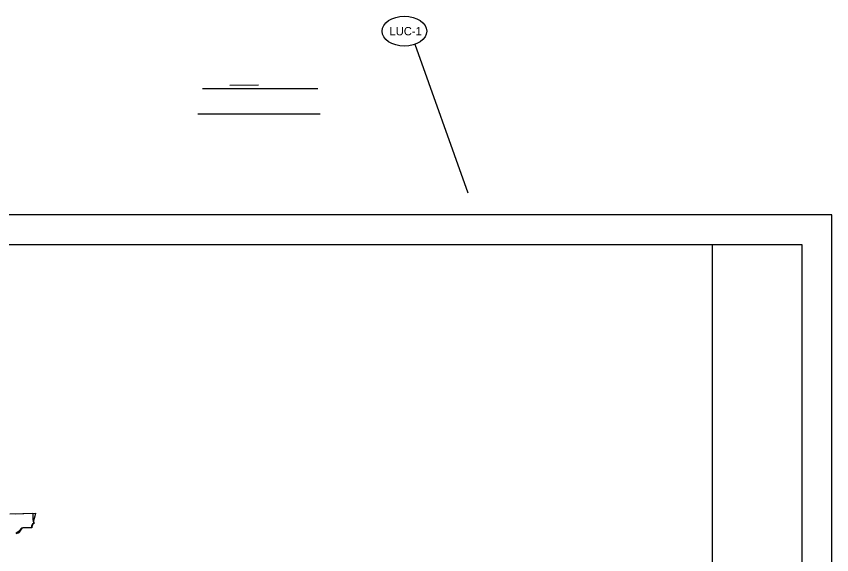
# Model space of a CAD drawing. Extents: x 0 to 750, y 0 to 507.
# Drawn here: x 406.4 to 680, y 325.9 to 506.7 of the extents above; entities that cross this region are included whole.
import ezdxf

# ---------------------------------------------------------------- set-up
doc = ezdxf.new("R2010")
doc.units = 0
for name, color, linetype in [('DV_X_Corp_Line', 7, 'Continuous'), ('GM_P_US_Alignment', 7, 'Continuous'), ('GM_X_County', 7, 'Continuous'), ('SH_Border', 7, 'Continuous'), ('SH_Cut_Line', 7, 'Continuous'), ('SH_Data', 7, 'Continuous')]:
    doc.layers.add(name, color=color, linetype=linetype)

msp = doc.modelspace()

# ---------------------------------------------------------------- linework, layer by layer
at = {"layer": 'DV_X_Corp_Line'}
msp.add_lwpolyline([(404.28, 339.61), (412.85, 339.79), (412.63, 338.77), (412.44, 338.08), (412.18, 337.26), (412.15, 336.86), (412.26, 336.42), (411.88, 336.1), (411.55, 335.51), (411.57, 334.86), (408.17, 334.75), (407.9, 334.52), (407.58, 334.15), (407.01, 333.56), (406.56, 333.16), (406.22, 332.99)], dxfattribs=at)
at = {"layer": 'GM_P_US_Alignment'}
for p, q in [((540.17, 497.28), (557.93, 447.44)), ((468.86, 482.45), (507.63, 482.45)), ((478.02, 483.53), (487.68, 483.63)), ((478.02, 483.53), (478.02, 483.53))]:
    msp.add_line(p, q, dxfattribs=at)
msp.add_ellipse((536.64, 501.69), major_axis=(7.5, 0), ratio=0.666667, dxfattribs=at)
at = {"layer": 'GM_X_County'}
msp.add_lwpolyline([(406.02, 339.64), (412.02, 339.77), (411.97, 339.44), (411.93, 338.93), (411.96, 338.37), (411.97, 338.14), (412.02, 337.96), (412.02, 337.65), (412, 337.61), (412.01, 337.55), (412.03, 337.42), (412.04, 337.23), (412.05, 337.18), (412.07, 337.12), (412.06, 336.99), (412.09, 336.94), (412.16, 336.93), (412.16, 336.84), (412.18, 336.77), (412.23, 336.72), (412.29, 336.69), (412.32, 336.67), (412.34, 336.64), (412.35, 336.58), (412.38, 336.54), (412.42, 336.49), (412.4, 336.42), (412.35, 336.37), (412.36, 336.41), (412.35, 336.46), (412.32, 336.48), (412.25, 336.47), (412.21, 336.44), (412.19, 336.38), (412.22, 336.34), (412.22, 336.32), (412.16, 336.28), (411.96, 336.19), (411.95, 336.11), (411.92, 336.06), (411.87, 336.01), (411.83, 335.95), (411.8, 335.86), (411.72, 335.52), (411.68, 335.11), (411.67, 334.98), (411.64, 334.93), (411.55, 334.88), (411.41, 334.88), (410.39, 334.89), (410.3, 334.89), (410.2, 334.85), (410.09, 334.86), (409.98, 334.89), (409.08, 334.89), (408.62, 334.84), (408.49, 334.81), (408.44, 334.76), (408.41, 334.7), (408.36, 334.65), (408.28, 334.62), (408.18, 334.58), (408.12, 334.54), (407.81, 334.08), (407.64, 333.78), (407.56, 333.65), (407.52, 333.55), (407.49, 333.43), (407.39, 333.33), (407.28, 333.25), (407.09, 333.14), (406.86, 333.07), (406.62, 332.96), (406.41, 332.83)], dxfattribs=at)
at = {"layer": 'SH_Border'}
msp.add_line((640, 10), (640, 430), dxfattribs=at)
msp.add_lwpolyline([(30, 430), (670, 430), (670, 10), (30, 10)], close=True, dxfattribs=at)
at = {"layer": 'SH_Cut_Line'}
msp.add_lwpolyline([(0, 0), (680, 0), (680, 440), (0, 440)], close=True, dxfattribs=at)
at = {"layer": 'SH_Data'}
msp.add_line((508.39, 473.83), (467.36, 473.83), dxfattribs=at)

# ---------------------------------------------------------------- texts
at = {"layer": 'GM_P_US_Alignment'}
msp.add_text('LUC-1', height=2.8, dxfattribs=at).set_placement((531.65, 500.29))

doc.saveas('drawing.dxf')
